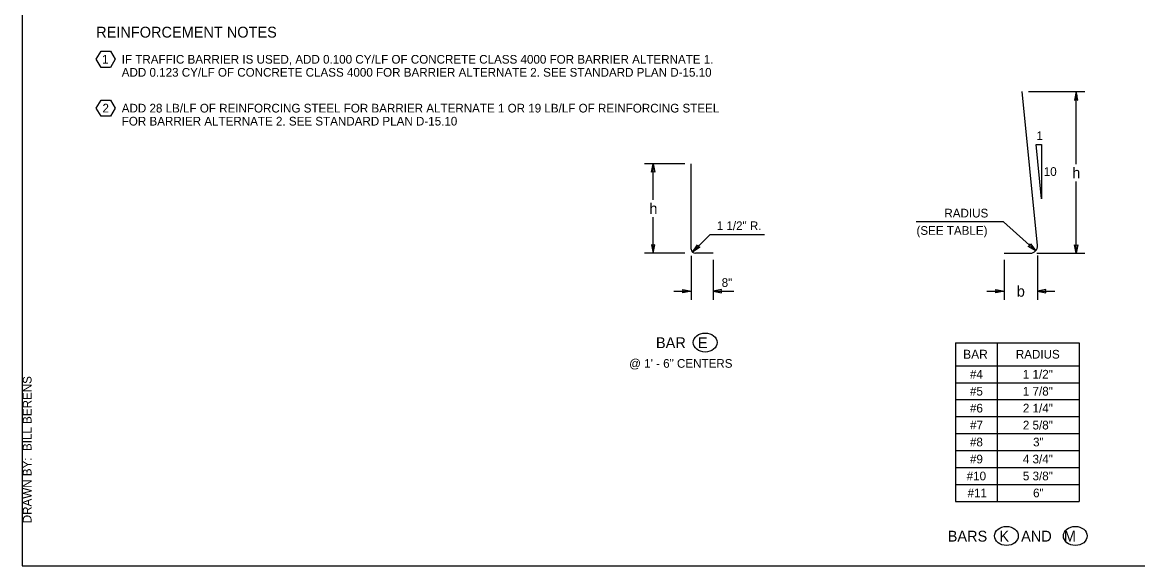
# Model space of a CAD drawing. Extents: x 99862 to 103151, y 100000 to 105076.
# Drawn here: x 99862 to 101917, y 103000 to 104001 of the extents above; entities that cross this region are included whole.
import ezdxf

# ---------------------------------------------------------------- set-up
doc = ezdxf.new("R2010")
doc.units = 0
for name, color, linetype in [('Level 1', 7, 'Continuous'), ('Level 13', 7, 'Continuous'), ('Level 15', 7, 'Continuous'), ('Level 20', 7, 'Continuous'), ('Level 21', 7, 'Continuous'), ('Level 4', 7, 'Continuous'), ('Level 5', 7, 'Continuous'), ('Level 60', 7, 'Continuous'), ('Level 62', 7, 'Continuous')]:
    doc.layers.add(name, color=color, linetype=linetype)

msp = doc.modelspace()

# ---------------------------------------------------------------- linework, layer by layer
at = {"layer": 'Level 1'}
msp.add_lwpolyline([(99862, 102999.5), (103151, 102999.5), (103151, 105075.5), (99862, 105075.5)], close=True, dxfattribs=at)
at = {"layer": 'Level 13'}
msp.add_arc((101719.3, 103588.3), 13.1, 270, 5.7106, dxfattribs=at)
at = {"layer": 'Level 15'}
for p, q in [((101716, 103873.3), (101819.8, 103873.3)), ((101803.8, 103739.3), (101803.8, 103873.3)), ((101729.7, 103775.7), (101739.7, 103775.7)), ((101739.7, 103675.7), (101729.7, 103775.7)), ((101739.7, 103775.7), (101739.7, 103675.7)), ((101082.6, 103740.1), (101008.6, 103740.1)), ((101024.6, 103673.6), (101024.6, 103740.1)), ((101803.8, 103575.1), (101803.8, 103707.3)), ((101024.6, 103575.1), (101024.6, 103641.6)), ((101669.7, 103633.1), (101508.9, 103633.1)), ((101669.7, 103633.1), (101729.1, 103579.5)), ((101129.4, 103609.9), (101096.8, 103577.3)), ((101129.4, 103609.9), (101229.5, 103609.9)), ((101082.6, 103575.1), (101008.6, 103575.1)), ((101731.3, 103575.1), (101819.8, 103575.1)), ((101094.6, 103570.6), (101094.6, 103489.1)), ((101134.6, 103563.1), (101134.6, 103489.1)), ((101671.3, 103563.1), (101671.3, 103489.1)), ((101732.4, 103571.1), (101732.4, 103489.1)), ((101062.6, 103505.1), (101094.6, 103505.1)), ((101134.6, 103505.1), (101173.2, 103505.1)), ((101639.3, 103505.1), (101671.3, 103505.1)), ((101732.4, 103505.1), (101764.4, 103505.1))]:
    msp.add_line(p, q, dxfattribs=at)
for points in [[(101803.8, 103873.3), (101800.7, 103857.5), (101803.8, 103858.3), (101806.9, 103857.5)], [(101803.8, 103873.3), (101802.3, 103865.4), (101803.8, 103865.8), (101805.4, 103865.4)], [(101024.6, 103740.1), (101027.7, 103724.4), (101024.6, 103725.1), (101021.5, 103724.4)], [(101024.6, 103575.1), (101027.7, 103590.9), (101024.6, 103590.1), (101021.5, 103590.9)], [(101096.8, 103577.3), (101105.8, 103590.6), (101107.4, 103587.9), (101110.1, 103586.3)], [(101729.1, 103579.5), (101715.3, 103587.7), (101717.9, 103589.5), (101719.5, 103592.3)], [(101803.8, 103575.1), (101800.7, 103590.9), (101803.8, 103590.1), (101806.9, 103590.9)], [(101094.6, 103505.1), (101078.9, 103502.1), (101079.6, 103505.1), (101078.9, 103508.2)], [(101134.6, 103505.1), (101150.3, 103502.1), (101149.6, 103505.1), (101150.3, 103508.2)], [(101671.3, 103505.1), (101655.6, 103502.1), (101656.3, 103505.1), (101655.6, 103508.2)], [(101732.4, 103505.1), (101748.1, 103502.1), (101747.4, 103505.1), (101748.1, 103508.2)]]:
    msp.add_lwpolyline(points, close=True, dxfattribs=at)
at = {"layer": 'Level 20'}
for points in [[(99998.3, 103932.5), (100007, 103947.5), (100024.3, 103947.5), (100033, 103932.5), (100024.3, 103917.5), (100007, 103917.5), (99998.3, 103932.5)], [(99998.3, 103842.5), (100007, 103857.5), (100024.3, 103857.5), (100033, 103842.5), (100024.3, 103827.5), (100007, 103827.5), (99998.3, 103842.5)]]:
    msp.add_lwpolyline(points, dxfattribs=at)
for centre in [(101120.2, 103410.7), (101675.2, 103054.3), (101802.1, 103054.3)]:
    msp.add_ellipse(centre, major_axis=(-21.9, 0), ratio=0.8, dxfattribs=at)
at = {"layer": 'Level 4'}
for p, q in [((101581.3, 103410.3), (101809.3, 103410.3)), ((101581.3, 103410.3), (101581.3, 103117.9)), ((101657.9, 103410.3), (101657.9, 103117.9)), ((101809.3, 103410.3), (101809.3, 103117.9)), ((101581.3, 103367.9), (101809.3, 103367.9)), ((101581.3, 103336.7), (101809.3, 103336.7)), ((101581.3, 103305.4), (101809.3, 103305.4)), ((101581.3, 103274.2), (101809.3, 103274.2)), ((101581.3, 103242.9), (101809.3, 103242.9)), ((101581.3, 103211.7), (101809.3, 103211.7)), ((101581.3, 103180.4), (101809.3, 103180.4)), ((101581.3, 103149.2), (101809.3, 103149.2)), ((101581.3, 103117.9), (101809.3, 103117.9))]:
    msp.add_line(p, q, dxfattribs=at)
at = {"layer": 'Level 5'}
for p, q in [((101732.4, 103589.6), (101704, 103873.3)), ((101094.6, 103582.6), (101094.6, 103740.1)), ((101134.6, 103575.1), (101102.1, 103575.1)), ((101671.3, 103575.1), (101719.3, 103575.1))]:
    msp.add_line(p, q, dxfattribs=at)
msp.add_arc((101102.1, 103582.6), 7.5, 180, 270, dxfattribs=at)
at = {"layer": 'Level 60'}
msp.add_line((99862, 102999.5), (99862, 102999.5), dxfattribs=at)

# ---------------------------------------------------------------- texts
at = {"layer": 'Level 20'}
for s, height, p in [('1', 16, (100008.8, 103924.5)), ('2', 16, (100009.7, 103834.5)), ('1', 16, (101730.6, 103783.7)), ('10', 16, (101744, 103717.7)), ('RADIUS', 16, (101560.9, 103641.1)), ('(SEE TABLE)', 16, (101509.5, 103609.1)), ('8"', 16, (101150.6, 103513.1)), ('b', 20, (101694.3, 103495.1)), ('BAR   E', 20, (101029.5, 103400.3)), ('BARS   K   AND   M', 20, (101567, 103043.9))]:
    msp.add_text(s, height=height, dxfattribs=at).set_placement(p)
for s, height, rotation, p in [('h', 20, 360, (101796.5, 103713.3)), ('h', 20, 360, (101017.3, 103647.6)), ('1 1/2" R.', 16, 359.9128, (101141.4, 103617.9))]:
    msp.add_text(s, height=height, rotation=rotation, dxfattribs=at).set_placement(p)
at = {"layer": 'Level 21'}
msp.add_text('@ 1\' - 6" CENTERS', height=16, dxfattribs=at).set_placement((100980.1, 103364.2))
at = {"layer": 'Level 4'}
for s, height, p in [('REINFORCEMENT NOTES', 20, (99998.1, 103972.5)), ('IF TRAFFIC BARRIER IS USED, ADD 0.100 CY/LF OF CONCRETE CLASS 4000 FOR BARRIER ALTERNATE 1. ', 16, (100045.2, 103924.5)), ('ADD 0.123 CY/LF OF CONCRETE CLASS 4000 FOR BARRIER ALTERNATE 2. SEE STANDARD PLAN D-15.10', 16, (100045.2, 103900.5)), ('ADD 28 LB/LF OF REINFORCING STEEL FOR BARRIER ALTERNATE 1 OR 19 LB/LF OF REINFORCING STEEL', 16, (100045.2, 103834.5)), ('FOR BARRIER ALTERNATE 2. SEE STANDARD PLAN D-15.10', 16, (100045.2, 103810.5)), ('BAR', 16.5, (101595.5, 103380.8)), ('RADIUS', 16, (101692.6, 103381.1)), ('#4', 16, (101608, 103344.3)), ('1 1/2"', 16, (101705.5, 103344.3)), ('#5', 16, (101608, 103313)), ('1 7/8"', 16, (101705.5, 103313)), ('#6', 16, (101608, 103281.8)), ('2 1/4"', 16, (101705.5, 103281.8)), ('#7', 16, (101608.2, 103250.5)), ('2 5/8"', 16, (101705.5, 103250.5)), ('#8', 16, (101608, 103219.3)), ('3"', 16, (101724.3, 103219.3)), ('4 3/4"', 16, (101705.5, 103188)), ('#9', 16, (101608, 103188)), ('#10', 16, (101602, 103156.8)), ('5 3/8"', 16, (101705.5, 103156.8)), ('#11', 16, (101603.5, 103125.5)), ('6"', 16, (101724.3, 103125.5))]:
    msp.add_text(s, height=height, dxfattribs=at).set_placement(p)
at = {"layer": 'Level 62'}
msp.add_text('DRAWN BY:  BILL BERENS', height=16, rotation=90, dxfattribs=at).set_placement((99879, 103077.7))

doc.saveas('drawing.dxf')
